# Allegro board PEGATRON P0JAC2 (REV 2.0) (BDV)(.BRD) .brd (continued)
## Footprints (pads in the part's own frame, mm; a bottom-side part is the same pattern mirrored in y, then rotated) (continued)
T_NB_HDMI_19P_16_4HL_RA_LF2
  rect 0.229x1.245 smd: 1(1.8,4.55) 3(1.4,4.55) 5(1,4.55) 7(0.6,4.55) 9(0.2,4.55) 11(-0.2,4.55) 13(-0.6,4.55) 15(-1,4.55) 17(-1.4,4.55) 19(-1.8,4.55)
  round 0.635 hole 0.381: 2(1.6,1.625) 4(1.2,3.225) 6(0.8,1.625) 8(0.4,3.225) 10(0,1.625) 12(-0.4,3.225) 14(-0.8,1.625) 16(-1.2,3.225) 18(-1.6,1.625)
  oval 0.965x2.159 hole 0.559: 20(4.2,2.425) 21(-4.2,2.425) 22(4.2,-2.425) 23(-4.2,-2.425)
TX_2R4P0402_H18
  rect 0.254x0.66 smd: 1(-0.325,-0.575) 2(-0.325,0.575) 3(0.325,-0.575) 4(0.325,0.575)
TX_BGA_6P_20_55X35
  round 0.305 smd: A1(-0.5,-0.25) A2(-0.5,0.25) B1(0,-0.25) B2(0,0.25) C1(0.5,-0.25) C2(0.5,0.25)
TX_BGA_8P_16_47X47
  round 0.229 smd: A1(-0.4,-0.4) A2(-0.4,0) A3(-0.4,0.4) B1(0,-0.4) B3(0,0.4) C1(0.4,-0.4) C2(0.4,0) C3(0.4,0.4)
TX_BGA_8P_20_75X35
  round 0.305 smd: A1(-0.75,-0.25) A2(-0.75,0.25) B1(-0.25,-0.25) B2(-0.25,0.25) C1(0.25,-0.25) C2(0.25,0.25) D1(0.75,-0.25) D2(0.75,0.25)
TX_BGA_12P_16_66X51
  round 0.229 smd: A1(-0.6,-0.4) A2(-0.6,0) A3(-0.6,0.4) B1(-0.2,-0.4) B2(-0.2,0) B3(-0.2,0.4) C1(0.2,-0.4) C2(0.2,0) C3(0.2,0.4) D1(0.6,-0.4) D2(0.6,0) D3(0.6,0.4)
TX_BGA_24P_20_118X118
  round 0.305 smd: A1(-1,-1) A2(-1,-0.5) A3(-1,0) A4(-1,0.5) A5(-1,1) B1(-0.5,-1) B3(-0.5,0) B4(-0.5,0.5) B5(-0.5,1) C1(0,-1) C2(0,-0.5) C3(0,0) C4(0,0.5) C5(0,1) D1(0.5,-1) D2(0.5,-0.5) D3(0.5,0) D4(0.5,0.5) D5(0.5,1) E1(1,-1) E2(1,-0.5) E3(1,0) E4(1,0.5) E5(1,1)
TX_BGA_169P_20_630X472_H39
  round 0.305 smd: A4(-6.75,-1.75) A6(-6.75,-0.75) A9(-6.75,0.75) A11(-6.75,1.75) AA1(3.25,-3.25) AA2(3.25,-2.75) AA3(3.25,-2.25) AA4(3.25,-1.75) AA5(3.25,-1.25) AA6(3.25,-0.75) AA7(3.25,-0.25) AA8(3.25,0.25) AA9(3.25,0.75) AA10(3.25,1.25) AA11(3.25,1.75) AA12(3.25,2.25) AA13(3.25,2.75) AA14(3.25,3.25) AE1(5.25,-3.25) AE14(5.25,3.25) AG2(6.25,-2.75) AG13(6.25,2.75) AH4(6.75,-1.75) AH6(6.75,-0.75) AH9(6.75,0.75) AH11(6.75,1.75) B2(-6.25,-2.75) B13(-6.25,2.75) D1(-5.25,-3.25) D14(-5.25,3.25) H1(-3.25,-3.25) H2(-3.25,-2.75) H3(-3.25,-2.25) H4(-3.25,-1.75) H5(-3.25,-1.25) H6(-3.25,-0.75) H7(-3.25,-0.25) H8(-3.25,0.25) H9(-3.25,0.75) H10(-3.25,1.25) H11(-3.25,1.75) H12(-3.25,2.25) H13(-3.25,2.75) H14(-3.25,3.25) J1(-2.75,-3.25) J2(-2.75,-2.75) J3(-2.75,-2.25) J4(-2.75,-1.75) J5(-2.75,-1.25) J6(-2.75,-0.75) J7(-2.75,-0.25) J8(-2.75,0.25) J9(-2.75,0.75) J10(-2.75,1.25) J11(-2.75,1.75) J12(-2.75,2.25) J13(-2.75,2.75) J14(-2.75,3.25) K1(-2.25,-3.25) K2(-2.25,-2.75) K3(-2.25,-2.25) K4(-2.25,-1.75) K5(-2.25,-1.25) K6(-2.25,-0.75) K7(-2.25,-0.25) K8(-2.25,0.25) K9(-2.25,0.75) K10(-2.25,1.25) K11(-2.25,1.75) K12(-2.25,2.25) K13(-2.25,2.75) K14(-2.25,3.25) L1(-1.75,-3.25) L2(-1.75,-2.75) L3(-1.75,-2.25) L4(-1.75,-1.75) L12(-1.75,2.25) L13(-1.75,2.75) L14(-1.75,3.25) M1(-1.25,-3.25) M2(-1.25,-2.75) M3(-1.25,-2.25) M5(-1.25,-1.25) M6(-1.25,-0.75) M7(-1.25,-0.25) M8(-1.25,0.25) M9(-1.25,0.75) M10(-1.25,1.25) M12(-1.25,2.25) M13(-1.25,2.75) M14(-1.25,3.25) N1(-0.75,-3.25) N2(-0.75,-2.75) N3(-0.75,-2.25) N5(-0.75,-1.25) N10(-0.75,1.25) N12(-0.75,2.25) N13(-0.75,2.75) N14(-0.75,3.25) P1(-0.25,-3.25) P2(-0.25,-2.75) P3(-0.25,-2.25) P5(-0.25,-1.25) P10(-0.25,1.25) P12(-0.25,2.25) P13(-0.25,2.75) P14(-0.25,3.25) R1(0.25,-3.25) R2(0.25,-2.75) R3(0.25,-2.25) R5(0.25,-1.25) R10(0.25,1.25) R12(0.25,2.25) R13(0.25,2.75) R14(0.25,3.25) T1(0.75,-3.25) T2(0.75,-2.75) T3(0.75,-2.25) T5(0.75,-1.25) T10(0.75,1.25) T12(0.75,2.25) T13(0.75,2.75) T14(0.75,3.25) U1(1.25,-3.25) U2(1.25,-2.75) U3(1.25,-2.25) U5(1.25,-1.25) U6(1.25,-0.75) U7(1.25,-0.25) U8(1.25,0.25) U9(1.25,0.75) U10(1.25,1.25) U12(1.25,2.25) U13(1.25,2.75) U14(1.25,3.25) V1(1.75,-3.25) V2(1.75,-2.75) V3(1.75,-2.25) V12(1.75,2.25) V13(1.75,2.75) V14(1.75,3.25) W1(2.25,-3.25) W2(2.25,-2.75) W3(2.25,-2.25) W4(2.25,-1.75) W5(2.25,-1.25) W6(2.25,-0.75) W7(2.25,-0.25) W8(2.25,0.25) W9(2.25,0.75) W10(2.25,1.25) W11(2.25,1.75) W12(2.25,2.25) W13(2.25,2.75) W14(2.25,3.25) Y1(2.75,-3.25) Y2(2.75,-2.75) Y3(2.75,-2.25) Y4(2.75,-1.75) Y5(2.75,-1.25) Y6(2.75,-0.75) Y7(2.75,-0.25) Y8(2.75,0.25) Y9(2.75,0.75) Y10(2.75,1.25) Y11(2.75,1.75) Y12(2.75,2.25) Y13(2.75,2.75) Y14(2.75,3.25)
TX_BGA_224P_16_244X244
  round 0.229 smd: A1(-2.8,-2.8) A2(-2.8,-2.4) A3(-2.8,-2) A4(-2.8,-1.6) A5(-2.8,-1.2) A6(-2.8,-0.8) A7(-2.8,-0.4) A8(-2.8,0) A9(-2.8,0.4) A10(-2.8,0.8) A11(-2.8,1.2) A12(-2.8,1.6) A13(-2.8,2) A14(-2.8,2.4) A15(-2.8,2.8) B1(-2.4,-2.8) B2(-2.4,-2.4) B3(-2.4,-2) B4(-2.4,-1.6) B5(-2.4,-1.2) B6(-2.4,-0.8) B7(-2.4,-0.4) B8(-2.4,0) B9(-2.4,0.4) B10(-2.4,0.8) B11(-2.4,1.2) B12(-2.4,1.6) B13(-2.4,2) B14(-2.4,2.4) B15(-2.4,2.8) C1(-2,-2.8) C2(-2,-2.4) C3(-2,-2) C4(-2,-1.6) C5(-2,-1.2) C6(-2,-0.8) C7(-2,-0.4) C8(-2,0) C9(-2,0.4) C10(-2,0.8) C11(-2,1.2) C12(-2,1.6) C13(-2,2) C14(-2,2.4) C15(-2,2.8) D1(-1.6,-2.8) D2(-1.6,-2.4) D3(-1.6,-2) D4(-1.6,-1.6) D5(-1.6,-1.2) D6(-1.6,-0.8) D7(-1.6,-0.4) D8(-1.6,0) D9(-1.6,0.4) D10(-1.6,0.8) D11(-1.6,1.2) D12(-1.6,1.6) D13(-1.6,2) D14(-1.6,2.4) D15(-1.6,2.8) E1(-1.2,-2.8) E2(-1.2,-2.4) E3(-1.2,-2) E4(-1.2,-1.6) E5(-1.2,-1.2) E6(-1.2,-0.8) E7(-1.2,-0.4) E8(-1.2,0) E9(-1.2,0.4) E10(-1.2,0.8) E11(-1.2,1.2) E12(-1.2,1.6) E13(-1.2,2) E14(-1.2,2.4) E15(-1.2,2.8) F1(-0.8,-2.8) F2(-0.8,-2.4) F3(-0.8,-2) F4(-0.8,-1.6) F5(-0.8,-1.2) F6(-0.8,-0.8) F7(-0.8,-0.4) F8(-0.8,0) F9(-0.8,0.4) F10(-0.8,0.8) F11(-0.8,1.2) F12(-0.8,1.6) F13(-0.8,2) F14(-0.8,2.4) F15(-0.8,2.8) G1(-0.4,-2.8) G2(-0.4,-2.4) G3(-0.4,-2) G4(-0.4,-1.6) G5(-0.4,-1.2) G6(-0.4,-0.8) G8(-0.4,0) G9(-0.4,0.4) G10(-0.4,0.8) G11(-0.4,1.2) G12(-0.4,1.6) G13(-0.4,2) G14(-0.4,2.4) G15(-0.4,2.8) H1(0,-2.8) H2(0,-2.4) H3(0,-2) H4(0,-1.6) H5(0,-1.2) H6(0,-0.8) H7(0,-0.4) H8(0,0) H9(0,0.4) H10(0,0.8) H11(0,1.2) H12(0,1.6) H13(0,2) H14(0,2.4) H15(0,2.8) J1(0.4,-2.8) J2(0.4,-2.4) J3(0.4,-2) J4(0.4,-1.6) J5(0.4,-1.2) J6(0.4,-0.8) J7(0.4,-0.4) J8(0.4,0) J9(0.4,0.4) J10(0.4,0.8) J11(0.4,1.2) J12(0.4,1.6) J13(0.4,2) J14(0.4,2.4) J15(0.4,2.8) K1(0.8,-2.8) K2(0.8,-2.4) K3(0.8,-2) K4(0.8,-1.6) K5(0.8,-1.2) K6(0.8,-0.8) K7(0.8,-0.4) K8(0.8,0) K9(0.8,0.4) K10(0.8,0.8) K11(0.8,1.2) K12(0.8,1.6) K13(0.8,2) K14(0.8,2.4) K15(0.8,2.8) L1(1.2,-2.8) L2(1.2,-2.4) L3(1.2,-2) L4(1.2,-1.6) L5(1.2,-1.2) L6(1.2,-0.8) L7(1.2,-0.4) L8(1.2,0) L9(1.2,0.4) L10(1.2,0.8) L11(1.2,1.2) L12(1.2,1.6) L13(1.2,2) L14(1.2,2.4) L15(1.2,2.8) M1(1.6,-2.8) M2(1.6,-2.4) M3(1.6,-2) M4(1.6,-1.6) M5(1.6,-1.2) M6(1.6,-0.8) M7(1.6,-0.4) M8(1.6,0) M9(1.6,0.4) M10(1.6,0.8) M11(1.6,1.2) M12(1.6,1.6) M13(1.6,2) M14(1.6,2.4) M15(1.6,2.8) N1(2,-2.8) N2(2,-2.4) N3(2,-2) N4(2,-1.6) N5(2,-1.2) N6(2,-0.8) N7(2,-0.4) N8(2,0) N9(2,0.4) N10(2,0.8) N11(2,1.2) N12(2,1.6) N13(2,2) N14(2,2.4) N15(2,2.8) P1(2.4,-2.8) P2(2.4,-2.4) P3(2.4,-2) P4(2.4,-1.6) P5(2.4,-1.2) P6(2.4,-0.8) P7(2.4,-0.4) P8(2.4,0) P9(2.4,0.4) P10(2.4,0.8) P11(2.4,1.2) P12(2.4,1.6) P13(2.4,2) P14(2.4,2.4) P15(2.4,2.8) R1(2.8,-2.8) R2(2.8,-2.4) R3(2.8,-2) R4(2.8,-1.6) R5(2.8,-1.2) R6(2.8,-0.8) R7(2.8,-0.4) R8(2.8,0) R9(2.8,0.4) R10(2.8,0.8) R11(2.8,1.2) R12(2.8,1.6) R13(2.8,2) R14(2.8,2.4) R15(2.8,2.8)
TX_BGA_253P_20_492X492
  round 0.305 smd: A1(-4,-4) A2(-4,-3.5) A3(-4,-3) A4(-4,-2.5) A5(-4,-2) A6(-4,-1.5) A7(-4,-1) A8(-4,-0.5) A9(-4,0) A10(-4,0.5) A11(-4,1) A12(-4,1.5) A13(-4,2) A14(-4,2.5) A15(-4,3) A16(-4,3.5) A17(-4,4) B1(-3.5,-4) B2(-3.5,-3.5) B3(-3.5,-3) B4(-3.5,-2.5) B5(-3.5,-2) B6(-3.5,-1.5) B7(-3.5,-1) B8(-3.5,-0.5) B9(-3.5,0) B10(-3.5,0.5) B11(-3.5,1) B12(-3.5,1.5) B13(-3.5,2) B14(-3.5,2.5) B15(-3.5,3) B16(-3.5,3.5) B17(-3.5,4) C1(-3,-4) C2(-3,-3.5) C3(-3,-3) C4(-3,-2.5) C5(-3,-2) C6(-3,-1.5) C7(-3,-1) C8(-3,-0.5) C9(-3,0) C10(-3,0.5) C11(-3,1) C12(-3,1.5) C13(-3,2) C14(-3,2.5) C15(-3,3) C16(-3,3.5) C17(-3,4) D1(-2.5,-4) D2(-2.5,-3.5) D3(-2.5,-3) D4(-2.5,-2.5) D5(-2.5,-2) D6(-2.5,-1.5) D7(-2.5,-1) D8(-2.5,-0.5) D9(-2.5,0) D10(-2.5,0.5) D11(-2.5,1) D12(-2.5,1.5) D13(-2.5,2) D14(-2.5,2.5) D15(-2.5,3) D16(-2.5,3.5) D17(-2.5,4) E1(-2,-4) E2(-2,-3.5) E3(-2,-3) E4(-2,-2.5) E5(-2,-2) E6(-2,-1.5) E7(-2,-1) E8(-2,-0.5) E9(-2,0) E10(-2,0.5) E11(-2,1) E12(-2,1.5) E13(-2,2) E14(-2,2.5) E15(-2,3) E16(-2,3.5) E17(-2,4) F1(-1.5,-4) F2(-1.5,-3.5) F3(-1.5,-3) F4(-1.5,-2.5) F5(-1.5,-2) F12(-1.5,1.5) F13(-1.5,2) F14(-1.5,2.5) F15(-1.5,3) F16(-1.5,3.5) F17(-1.5,4) G1(-1,-4) G2(-1,-3.5) G3(-1,-3) G4(-1,-2.5) G5(-1,-2) G12(-1,1.5) G13(-1,2) G14(-1,2.5) G15(-1,3) G16(-1,3.5) G17(-1,4) H1(-0.5,-4) H2(-0.5,-3.5) H3(-0.5,-3) H4(-0.5,-2.5) H5(-0.5,-2) H12(-0.5,1.5) H13(-0.5,2) H14(-0.5,2.5) H15(-0.5,3) H16(-0.5,3.5) H17(-0.5,4) J1(0,-4) J2(0,-3.5) J3(0,-3) J4(0,-2.5) J5(0,-2) J12(0,1.5) J13(0,2) J14(0,2.5) J15(0,3) J16(0,3.5) J17(0,4) K1(0.5,-4) K2(0.5,-3.5) K3(0.5,-3) K4(0.5,-2.5) K5(0.5,-2) K12(0.5,1.5) K13(0.5,2) K14(0.5,2.5) K15(0.5,3) K16(0.5,3.5) K17(0.5,4) L1(1,-4) L2(1,-3.5) L3(1,-3) L4(1,-2.5) L5(1,-2) L12(1,1.5) L13(1,2) L14(1,2.5) L15(1,3) L16(1,3.5) L17(1,4) M1(1.5,-4) M2(1.5,-3.5) M3(1.5,-3) M4(1.5,-2.5) M5(1.5,-2) M6(1.5,-1.5) M7(1.5,-1) M8(1.5,-0.5) M9(1.5,0) M10(1.5,0.5) M11(1.5,1) M12(1.5,1.5) M13(1.5,2) M14(1.5,2.5) M15(1.5,3) M16(1.5,3.5) M17(1.5,4) N1(2,-4) N2(2,-3.5) N3(2,-3) N4(2,-2.5) N5(2,-2) N6(2,-1.5) N7(2,-1) N8(2,-0.5) N9(2,0) N10(2,0.5) N11(2,1) N12(2,1.5) N13(2,2) N14(2,2.5) N15(2,3) N16(2,3.5) N17(2,4) P1(2.5,-4) P2(2.5,-3.5) P3(2.5,-3) P4(2.5,-2.5) P5(2.5,-2) P6(2.5,-1.5) P7(2.5,-1) P8(2.5,-0.5) P9(2.5,0) P10(2.5,0.5) P11(2.5,1) P12(2.5,1.5) P13(2.5,2) P14(2.5,2.5) P15(2.5,3) P16(2.5,3.5) P17(2.5,4) R1(3,-4) R2(3,-3.5) R3(3,-3) R4(3,-2.5) R5(3,-2) R6(3,-1.5) R7(3,-1) R8(3,-0.5) R9(3,0) R10(3,0.5) R11(3,1) R12(3,1.5) R13(3,2) R14(3,2.5) R15(3,3) R16(3,3.5) R17(3,4) T1(3.5,-4) T2(3.5,-3.5) T3(3.5,-3) T4(3.5,-2.5) T5(3.5,-2) T6(3.5,-1.5) T7(3.5,-1) T8(3.5,-0.5) T9(3.5,0) T10(3.5,0.5) T11(3.5,1) T12(3.5,1.5) T13(3.5,2) T14(3.5,2.5) T15(3.5,3) T16(3.5,3.5) T17(3.5,4) U1(4,-4) U2(4,-3.5) U3(4,-3) U4(4,-2.5) U5(4,-2) U6(4,-1.5) U7(4,-1) U8(4,-0.5) U9(4,0) U10(4,0.5) U11(4,1) U12(4,1.5) U13(4,2) U14(4,2.5) U15(4,3) U16(4,3.5) U17(4,4)
TX_BTOB_60P_16_4H_F_PANA
  rect 0.229x0.508 smd: 1(-5.8,-1.05) 2(-5.8,1.05) 3(-5.4,-1.05) 4(-5.4,1.05) 5(-5,-1.05) 6(-5,1.05) 7(-4.6,-1.05) 8(-4.6,1.05) 9(-4.2,-1.05) 10(-4.2,1.05) 11(-3.8,-1.05) 12(-3.8,1.05) 13(-3.4,-1.05) 14(-3.4,1.05) 15(-3,-1.05) 16(-3,1.05) 17(-2.6,-1.05) 18(-2.6,1.05) 19(-2.2,-1.05) 20(-2.2,1.05) 21(-1.8,-1.05) 22(-1.8,1.05) 23(-1.4,-1.05) 24(-1.4,1.05) 25(-1,-1.05) 26(-1,1.05) 27(-0.6,-1.05) 28(-0.6,1.05) 29(-0.2,-1.05) 30(-0.2,1.05) 31(0.2,-1.05) 32(0.2,1.05) 33(0.6,-1.05) 34(0.6,1.05) 35(1,-1.05) 36(1,1.05) 37(1.4,-1.05) 38(1.4,1.05) 39(1.8,-1.05) 40(1.8,1.05) 41(2.2,-1.05) 42(2.2,1.05) 43(2.6,-1.05) 44(2.6,1.05) 45(3,-1.05) 46(3,1.05) 47(3.4,-1.05) 48(3.4,1.05) 49(3.8,-1.05) 50(3.8,1.05) 51(4.2,-1.05) 52(4.2,1.05) 53(4.6,-1.05) 54(4.6,1.05) 55(5,-1.05) 56(5,1.05) 57(5.4,-1.05) 58(5.4,1.05) 59(5.8,-1.05) 60(5.8,1.05)
  rect 0.787x0.787 smd: 61(6.85,-0.91) 62(-6.85,-0.91) 63(6.85,0.91) 64(-6.85,0.91)
TX_C0201
  rect 0.305x0.305 smd: 1(-0.254,0) 2(0.254,0)
TX_C0201_H14
  rect 0.305x0.305 smd: 1(-0.254,0) 2(0.254,0)
TX_C0402
  rect 0.432x0.508 smd: 1(-0.432,0) 2(0.432,0)
TX_C0402_H24
  rect 0.432x0.508 smd: 1(-0.432,0) 2(0.432,0)
TX_C0402_H26
  rect 0.432x0.508 smd: 1(-0.432,0) 2(0.432,0)
TX_C0402_H28
  rect 0.432x0.508 smd: 1(-0.432,0) 2(0.432,0)
TX_C0603
  rect 0.559x0.889 smd: 1(-0.67,0) 2(0.67,0)
TX_C0603_H37
  rect 0.559x0.889 smd: 1(-0.67,0) 2(0.67,0)
TX_C0603_H39
  rect 0.559x0.889 smd: 1(-0.67,0) 2(0.67,0)
TX_C0805
  rect 0.813x1.397 smd: 1(0.9,0) 2(-0.9,0)
TX_C0805_H49
  rect 0.813x1.397 smd: 1(0.9,0) 2(-0.9,0)
TX_C3216_H47
  rect 1.803x1.194 smd: 1(1.613,0) 2(-1.613,0)
TX_C3528_SANYO_H47
  rect 1.422x2.21 smd: 1(1.567,0) 2(-1.567,0)
TX_CHOKE_4P_49X39
  rect 0.711x0.305 smd: 1(-0.625,0.275) 2(0.625,0.275) 3(0.625,-0.275) 4(-0.625,-0.275)
TX_DFN1006_2
  rect 0.406x0.711 smd: 1(-0.35,0) 2(0.35,0)
TX_DFN_6P_26_79X79_2PAD_IR
  rect 0.381x0.457 smd: 1(-0.65,-0.925) 2(0,-0.925) 3(0.65,-0.925) 4(0.65,0.925) 5(0,0.925) 6(-0.65,0.925)
  rect 1.041x0.965 smd: 7(-0.28,0.002)
  rect 0.229x0.787 smd: 8(0.735,0.002)
TX_DFN_6P_26_S79_2PAD_H31
  rect 0.381x0.457 smd: 1(-0.65,-0.922) 2(0,-0.922) 3(0.65,-0.922) 4(0.65,0.922) 5(0,0.922) 6(-0.65,0.922)
  rect 1.092x0.965 smd: 7(-0.23,0)
  rect 0.203x0.838 smd: 8(0.716,-0.005)
TX_DFN_8P_18_79X79
  rect 0.279x0.711 smd: 1(-0.675,-0.799)
  rect 0.279x0.61 smd: 2(-0.225,-0.85) 3(0.225,-0.85) 4(0.675,-0.85) 5(0.675,0.85) 6(0.225,0.85) 7(-0.225,0.85) 8(-0.675,0.85)
TX_DFN_8P_50_197X236_PAD_WI
  rect 0.406x1.067 smd: 1(-1.905,-2.833) 2(-0.635,-2.833) 3(0.635,-2.833) 4(1.905,-2.833) 5(1.905,2.833) 6(0.635,2.833) 7(-0.635,2.833) 8(-1.905,2.833)
  rect 4.343x3.454 smd: 9(0,0)
TX_DIODE_2P_39X24_INFINEON
  rect 0.356x0.61 smd: 1(-0.325,0) 2(0.325,0)
TX_ESD_2P_33_39X24_H20
  rect 0.559x0.61 smd: 1(-0.425,0) 2(0.425,0)
TX_FPC_6P_20_2HOLD_ACES
  rect 0.305x0.787 smd: 1(-1.25,2.5) 2(-0.75,2.5) 3(-0.25,2.5) 4(0.25,2.5) 5(0.75,2.5) 6(1.25,2.5)
  rect 0.406x0.787 smd: 7(-2.25,0) 8(2.25,0)
TX_FPC_12P_20_2HOLD_RA_PTWO
  rect 0.305x0.711 smd: 1(-2.75,2.745) 2(-2.25,2.745) 3(-1.75,2.745) 4(-1.25,2.745) 5(-0.75,2.745) 6(-0.25,2.745) 7(0.25,2.745) 8(0.75,2.745) 9(1.25,2.745) 10(1.75,2.745) 11(2.25,2.745) 12(2.75,2.745)
  rect 0.406x0.889 smd: 13(-3.62,0) 14(3.62,0)
TX_FPC_18P_20_2H_RA_B
  rect 0.305x0.787 smd: 1(-4.25,2.5) 2(-3.75,2.5) 3(-3.25,2.5) 4(-2.75,2.5) 5(-2.25,2.5) 6(-1.75,2.5) 7(-1.25,2.5) 8(-0.75,2.5) 9(-0.25,2.5) 10(0.25,2.5) 11(0.75,2.5) 12(1.25,2.5) 13(1.75,2.5) 14(2.25,2.5) 15(2.75,2.5) 16(3.25,2.5) 17(3.75,2.5) 18(4.25,2.5)
  rect 0.406x0.787 smd: 19(-5.25,0) 20(5.25,0)
TX_FPC_21P_24_2H_RA_SUNG
  rect 0.305x0.787 smd: 1(-3,-0.375) 3(-2.4,-0.375) 5(-1.8,-0.375) 7(-1.2,-0.375) 9(-0.6,-0.375) 11(0,-0.375) 13(0.6,-0.375) 15(1.2,-0.375) 17(1.8,-0.375) 19(2.4,-0.375) 21(3,-0.375)
  rect 0.305x0.66 smd: 2(-2.7,2.5) 4(-2.1,2.5) 6(-1.5,2.5) 8(-0.9,2.5) 10(-0.3,2.5) 12(0.3,2.5) 14(0.9,2.5) 16(1.5,2.5) 18(2.1,2.5) 20(2.7,2.5)
  rect 0.305x1.143 smd: 22(-3.65,0) 23(3.65,0)
TX_FPC_39P_24_2HOLD_RA_HSR
  rect 0.305x0.787 smd: 1(-5.7,-0.275) 3(-5.1,-0.275) 5(-4.5,-0.275) 7(-3.9,-0.275) 9(-3.3,-0.275) 11(-2.7,-0.275) 13(-2.1,-0.275) 15(-1.5,-0.275) 17(-0.9,-0.275) 19(-0.3,-0.275) 21(0.3,-0.275) 23(0.9,-0.275) 25(1.5,-0.275) 27(2.1,-0.275) 29(2.7,-0.275) 31(3.3,-0.275) 33(3.9,-0.275) 35(4.5,-0.275) 37(5.1,-0.275) 39(5.7,-0.275)
  rect 0.305x0.66 smd: 2(-5.4,2.6) 4(-4.8,2.6) 6(-4.2,2.6) 8(-3.6,2.6) 10(-3,2.6) 12(-2.4,2.6) 14(-1.8,2.6) 16(-1.2,2.6) 18(-0.6,2.6) 20(0,2.6) 22(0.6,2.6) 24(1.2,2.6) 26(1.8,2.6) 28(2.4,2.6) 30(3,2.6) 32(3.6,2.6) 34(4.2,2.6) 36(4.8,2.6) 38(5.4,2.6)
  rect 0.406x0.94 smd: 40(-6.4,0) 41(6.4,0)
TX_FPC_CON_34P_31_2HD_T
  rect 0.508x1.092 smd: 1(-13.2,1.65) 2(-12.4,1.65) 3(-11.6,1.65) 4(-10.8,1.65) 5(-10,1.65) 6(-9.2,1.65) 7(-8.4,1.65) 8(-7.6,1.65) 9(-6.8,1.65) 10(-6,1.65) 11(-5.2,1.65) 12(-4.4,1.65) 13(-3.6,1.65) 14(-2.8,1.65) 15(-2,1.65) 16(-1.2,1.65) 17(-0.4,1.65) 18(0.4,1.65) 19(1.2,1.65) 20(2,1.65) 21(2.8,1.65) 22(3.6,1.65) 23(4.4,1.65) 24(5.2,1.65) 25(6,1.65) 26(6.8,1.65) 27(7.6,1.65) 28(8.4,1.65) 29(9.2,1.65) 30(10,1.65) 31(10.8,1.65) 32(11.6,1.65) 33(12.4,1.65) 34(13.2,1.65)
  rect 2.388x2.21 smd: 35(15.6,0) 36(-15.6,0)
TX_FUSE_2P_39X20_H14
  rect 0.584x0.559 smd: 1(-0.483,0) 2(0.483,0)
TX_INDUCTOR_2P_98X79_TAIYO
  rect 0.787x2.007 smd: 1(-1,0) 2(1,0)
TX_INDUCTOR_2P_213X205_H59
  rect 1.905x2.489 smd: 1(-2.047,0) 2(2.047,0)
TX_L0402_H24
  rect 0.432x0.508 smd: 1(-0.432,0) 2(0.432,0)
TX_L0603_H26
  rect 0.559x0.889 smd: 1(-0.775,0) 2(0.775,0)
TX_L0805_H43
  rect 0.813x1.397 smd: 1(-0.9,0) 2(0.9,0)
TX_L1008_MURA
  rect 1.321x2.007 smd: 1(-1.217,0) 2(1.217,0)
TX_L1008_TAIYO_H47
  rect 1.245x2.007 smd: 1(-1.267,0) 2(1.267,0)
TX_LGA_96P_20_12PAD_FOXCO
  rect 0.305x0.508 smd: 1(-6.75,-5.6) 2(-6.25,-5.6) 3(-5.75,-5.6) 4(-5.25,-5.6) 5(-4.75,-5.6) 6(-4.25,-5.6) 7(-3.75,-5.6) 8(-3.25,-5.6) 9(-2.75,-5.6) 10(-2.25,-5.6) 11(-1.75,-5.6) 12(-1.25,-5.6) 13(-0.75,-5.6) 14(-0.25,-5.6) 15(0.25,-5.6) 16(0.75,-5.6) 17(1.25,-5.6) 18(1.75,-5.6) 19(2.25,-5.6) 20(2.75,-5.6) 21(3.25,-5.6) 22(3.75,-5.6) 23(4.25,-5.6) 24(4.75,-5.6) 25(5.25,-5.6) 26(5.75,-5.6) 27(6.25,-5.6) 28(6.75,-5.6) 49(6.75,5.6) 50(6.25,5.6) 51(5.75,5.6) 52(5.25,5.6) 53(4.75,5.6) 54(4.25,5.6) 55(3.75,5.6) 56(3.25,5.6) 57(2.75,5.6) 58(2.25,5.6) 59(1.75,5.6) 60(1.25,5.6) 61(0.75,5.6) 62(0.25,5.6) 63(-0.25,5.6) 64(-0.75,5.6) 65(-1.25,5.6) 66(-1.75,5.6) 67(-2.25,5.6) 68(-2.75,5.6) 69(-3.25,5.6) 70(-3.75,5.6) 71(-4.25,5.6) 72(-4.75,5.6) 73(-5.25,5.6) 74(-5.75,5.6) 75(-6.25,5.6) 76(-6.75,5.6)
  rect 0.508x0.305 smd: 29(7.6,-4.75) 30(7.6,-4.25) 31(7.6,-3.75) 32(7.6,-3.25) 33(7.6,-2.75) 34(7.6,-2.25) 35(7.6,-1.75) 36(7.6,-1.25) 37(7.6,-0.75) 38(7.6,-0.25) 39(7.6,0.25) 40(7.6,0.75) 41(7.6,1.25) 42(7.6,1.75) 43(7.6,2.25) 44(7.6,2.75) 45(7.6,3.25) 46(7.6,3.75) 47(7.6,4.25) 48(7.6,4.75) 77(-7.6,4.75) 78(-7.6,4.25) 79(-7.6,3.75) 80(-7.6,3.25) 81(-7.6,2.75) 82(-7.6,2.25) 83(-7.6,1.75) 84(-7.6,1.25) 85(-7.6,0.75) 86(-7.6,0.25) 87(-7.6,-0.25) 88(-7.6,-0.75) 89(-7.6,-1.25) 90(-7.6,-1.75) 91(-7.6,-2.25) 92(-7.6,-2.75) 93(-7.6,-3.25) 94(-7.6,-3.75) 95(-7.6,-4.25) 96(-7.6,-4.75)
  rect 0.711x0.711 smd: G1(-7.5,-5.5) G2(7.5,-5.5) G3(7.5,5.5) G4(-7.5,5.5)
  rect 2.997x2.997 smd: G5(-4.95,-1.65) G6(-1.65,-1.65) G7(1.65,-1.65) G8(4.95,-1.65) G9(-4.95,1.65) G10(-1.65,1.65) G11(1.65,1.65) G12(4.95,1.65)
TX_MICRO_SD_8P_11HOLD
  rect 0.66x0.991 smd: 1(2.3,7.425) 2(1.4,7.425) 3(0.5,7.425) 4(-0.4,7.425) 5(-1.3,7.425) 6(-2.2,7.425) 7(-3.1,7.425) 8(-4,7.425)
  rect 0.991x0.838 smd: 9(6.975,-4.4) 10(-6.975,-4.4) 13(-6.975,-2.475)
  rect 0.889x1.702 smd: 11(-7.15,7.075) 14(-7.15,-6.625) 15(7.15,7.075) 18(7.15,-6.625)
  rect 0.94x1.397 smd: 12(-7,0.475)
  rect 1.118x1.397 smd: 16(6.735,3.175)
  rect 0.813x1.397 smd: 17(6.887,-2.275)
  rect 0.889x0.991 smd: 19(-5.575,7.425)
TX_MICROPHONE_6P_148X186_KN
  round 0.914 smd: 1(-1.17,1.65) 2(-1.17,0) 3(-1.17,-1.65) 4(1.17,-1.65) 5(1.17,0)
  custom 0.28x0.28 smd: 6(1.17,1.65)
TX_OPLGA_6P_24_71X93_CAPELL
  rect 0.406x0.991 smd: 1(-0.6,-1.125) 2(0,-1.125) 3(0.6,-1.125) 4(0.6,1.125) 5(0,1.125) 6(-0.6,1.125)
TX_POWERDI123
  rect 0.889x1.397 smd: 1(-1.605,0)
  rect 2.21x1.397 smd: 2(0.945,0)
TX_QFN_10P_20_79X61
  rect 0.33x0.508 smd: 1(-0.775,-0.595)
  rect 0.279x0.508 smd: 2(-0.25,-0.595) 3(0.25,-0.595) 4(0.75,-0.595) 6(0.75,0.595) 7(0.25,0.595) 8(-0.25,0.595) 9(-0.75,0.595)
  rect 0.508x0.279 smd: 5(0.82,0) 10(-0.82,0)
TX_QFN_16P_20_S118_P_KT_5V
  rect 0.279x0.61 smd: 1(-0.75,-1.35) 2(-0.25,-1.35) 3(0.25,-1.35) 4(0.75,-1.35) 9(0.75,1.35) 10(0.25,1.35) 11(-0.25,1.35) 12(-0.75,1.35)
  rect 0.61x0.279 smd: 5(1.35,-0.75) 6(1.35,-0.25) 7(1.35,0.25) 8(1.35,0.75) 13(-1.35,0.75) 14(-1.35,0.25) 15(-1.35,-0.25) 16(-1.35,-0.75)
  rect 1.727x1.727 smd: 17(0,0)
  round 0.61 hole 0.305: 18(-0.5,0.5) 19(0.5,0.5) 20(0,0) 21(-0.5,-0.5) 22(0.5,-0.5)
TX_QFN_16P_26_S157_PD_TI_4V
  rect 0.381x0.61 smd: 1(-0.975,-1.85) 2(-0.325,-1.85) 3(0.325,-1.85) 4(0.975,-1.85) 9(0.975,1.85) 10(0.325,1.85) 11(-0.325,1.85) 12(-0.975,1.85)
  rect 0.61x0.381 smd: 5(1.85,-0.975) 6(1.85,-0.325) 7(1.85,0.325) 8(1.85,0.975) 13(-1.85,0.975) 14(-1.85,0.325) 15(-1.85,-0.325) 16(-1.85,-0.975)
  rect 2.642x2.642 smd: 17(0,0)
  round 0.61 hole 0.305: 18(-1.016,1.016) 19(1.016,1.016) 20(-1.016,-1.016) 21(1.016,-1.016)
TX_QFN_24P_16_S118_P_INVH37
  rect 0.229x0.406 smd: 1(-1,-1.447) 6(1,-1.447) 13(1,1.447) 18(-1,1.447)
  rect 0.229x0.508 smd: 2(-0.6,-1.396) 3(-0.2,-1.396) 4(0.2,-1.396) 5(0.6,-1.396) 14(0.6,1.396) 15(0.2,1.396) 16(-0.2,1.396) 17(-0.6,1.396)
  rect 0.406x0.229 smd: 7(1.447,-1) 12(1.447,1) 19(-1.447,1) 24(-1.447,-1)
  rect 0.508x0.229 smd: 8(1.396,-0.6) 9(1.396,-0.2) 10(1.396,0.2) 11(1.396,0.6) 20(-1.396,0.6) 21(-1.396,0.2) 22(-1.396,-0.2) 23(-1.396,-0.6)
TX_QFN_24P_20_S157_P_QU_4V
  rect 0.279x0.61 smd: 1(-1.25,-1.85) 2(-0.75,-1.85) 3(-0.25,-1.85) 4(0.25,-1.85) 5(0.75,-1.85) 6(1.25,-1.85) 13(1.25,1.85) 14(0.75,1.85) 15(0.25,1.85) 16(-0.25,1.85) 17(-0.75,1.85) 18(-1.25,1.85)
  rect 0.61x0.279 smd: 7(1.85,-1.25) 8(1.85,-0.75) 9(1.85,-0.25) 10(1.85,0.25) 11(1.85,0.75) 12(1.85,1.25) 19(-1.85,1.25) 20(-1.85,0.75) 21(-1.85,0.25) 22(-1.85,-0.25) 23(-1.85,-0.75) 24(-1.85,-1.25)
  rect 2.743x2.743 smd: 25(0,0)
  round 0.61 hole 0.305: 26(-1.067,1.067) 27(1.067,1.067) 28(-1.067,-1.067) 29(1.067,-1.067)
TX_QFN_48P_16_S236_P_RE_10V
  rect 0.229x0.61 smd: 1(-2.2,-2.85) 2(-1.8,-2.85) 3(-1.4,-2.85) 4(-1,-2.85) 5(-0.6,-2.85) 6(-0.2,-2.85) 7(0.2,-2.85) 8(0.6,-2.85) 9(1,-2.85) 10(1.4,-2.85) 11(1.8,-2.85) 12(2.2,-2.85) 25(2.2,2.85) 26(1.8,2.85) 27(1.4,2.85) 28(1,2.85) 29(0.6,2.85) 30(0.2,2.85) 31(-0.2,2.85) 32(-0.6,2.85) 33(-1,2.85) 34(-1.4,2.85) 35(-1.8,2.85) 36(-2.2,2.85)
  rect 0.61x0.229 smd: 13(2.85,-2.2) 14(2.85,-1.8) 15(2.85,-1.4) 16(2.85,-1) 17(2.85,-0.6) 18(2.85,-0.2) 19(2.85,0.2) 20(2.85,0.6) 21(2.85,1) 22(2.85,1.4) 23(2.85,1.8) 24(2.85,2.2) 37(-2.85,2.2) 38(-2.85,1.8) 39(-2.85,1.4) 40(-2.85,1) 41(-2.85,0.6) 42(-2.85,0.2) 43(-2.85,-0.2) 44(-2.85,-0.6) 45(-2.85,-1) 46(-2.85,-1.4) 47(-2.85,-1.8) 48(-2.85,-2.2)
  rect 4.648x4.648 smd: 49(0,0)
  round 0.61 hole 0.305: 50(-2.019,2.019) 51(0,2.019) 52(2.019,2.019) 53(-2.019,0) 54(-0.673,0) 55(0.673,0) 56(2.019,0) 57(-2.019,-2.019) 58(0,-2.019) 59(2.019,-2.019)
TX_QFN_48P_20_S276_P_QL_16V
  rect 0.279x0.61 smd: 1(-2.75,-3.35) 2(-2.25,-3.35) 3(-1.75,-3.35) 4(-1.25,-3.35) 5(-0.75,-3.35) 6(-0.25,-3.35) 7(0.25,-3.35) 8(0.75,-3.35) 9(1.25,-3.35) 10(1.75,-3.35) 11(2.25,-3.35) 12(2.75,-3.35) 25(2.75,3.35) 26(2.25,3.35) 27(1.75,3.35) 28(1.25,3.35) 29(0.75,3.35) 30(0.25,3.35) 31(-0.25,3.35) 32(-0.75,3.35) 33(-1.25,3.35) 34(-1.75,3.35) 35(-2.25,3.35) 36(-2.75,3.35)
  rect 0.61x0.279 smd: 13(3.35,-2.75) 14(3.35,-2.25) 15(3.35,-1.75) 16(3.35,-1.25) 17(3.35,-0.75) 18(3.35,-0.25) 19(3.35,0.25) 20(3.35,0.75) 21(3.35,1.25) 22(3.35,1.75) 23(3.35,2.25) 24(3.35,2.75) 37(-3.35,2.75) 38(-3.35,2.25) 39(-3.35,1.75) 40(-3.35,1.25) 41(-3.35,0.75) 42(-3.35,0.25) 43(-3.35,-0.25) 44(-3.35,-0.75) 45(-3.35,-1.25) 46(-3.35,-1.75) 47(-3.35,-2.25) 48(-3.35,-2.75)
  rect 5.309x5.309 smd: 49(0,0)
  round 0.61 hole 0.305: 50(-1.5,1.5) 51(-0.5,1.5) 52(0.5,1.5) 53(1.5,1.5) 54(1.5,0.5) 55(0.5,0.5) 56(-0.5,0.5) 57(-1.5,0.5) 58(-1.5,-0.5) 59(-0.5,-0.5) 60(0.5,-0.5) 61(1.5,-0.5) 62(1.5,-1.5) 63(0.5,-1.5) 64(-0.5,-1.5) 65(-1.5,-1.5)
TX_QFP_64P_16_354X354_H63
  rect 0.229x1.499 smd: 1(-3,-4.36) 2(-2.6,-4.36) 3(-2.2,-4.36) 4(-1.8,-4.36) 5(-1.4,-4.36) 6(-1,-4.36) 7(-0.6,-4.36) 8(-0.2,-4.36) 9(0.2,-4.36) 10(0.6,-4.36) 11(1,-4.36) 12(1.4,-4.36) 13(1.8,-4.36) 14(2.2,-4.36) 15(2.6,-4.36) 16(3,-4.36) 33(3,4.36) 34(2.6,4.36) 35(2.2,4.36) 36(1.8,4.36) 37(1.4,4.36) 38(1,4.36) 39(0.6,4.36) 40(0.2,4.36) 41(-0.2,4.36) 42(-0.6,4.36) 43(-1,4.36) 44(-1.4,4.36) 45(-1.8,4.36) 46(-2.2,4.36) 47(-2.6,4.36) 48(-3,4.36)
  rect 1.499x0.229 smd: 17(4.36,-3) 18(4.36,-2.6) 19(4.36,-2.2) 20(4.36,-1.8) 21(4.36,-1.4) 22(4.36,-1) 23(4.36,-0.6) 24(4.36,-0.2) 25(4.36,0.2) 26(4.36,0.6) 27(4.36,1) 28(4.36,1.4) 29(4.36,1.8) 30(4.36,2.2) 31(4.36,2.6) 32(4.36,3) 49(-4.36,3) 50(-4.36,2.6) 51(-4.36,2.2) 52(-4.36,1.8) 53(-4.36,1.4) 54(-4.36,1) 55(-4.36,0.6) 56(-4.36,0.2) 57(-4.36,-0.2) 58(-4.36,-0.6) 59(-4.36,-1) 60(-4.36,-1.4) 61(-4.36,-1.8) 62(-4.36,-2.2) 63(-4.36,-2.6) 64(-4.36,-3)
TX_R0201_0OHM_H10
  rect 0.305x0.305 smd: 1(-0.254,0) 2(0.254,0)
TX_R0201_H10
  rect 0.305x0.305 smd: 1(-0.254,0) 2(0.254,0)
TX_R0402
  rect 0.432x0.508 smd: 1(-0.432,0) 2(0.432,0)
TX_R0402_0OHM
  rect 0.432x0.508 smd: 1(-0.432,0) 2(0.432,0)
TX_R0402_H22
  rect 0.432x0.508 smd: 1(-0.432,0) 2(0.432,0)
TX_R0402_SHORT_12MIL
  rect 0.457x0.508 smd: 1(-0.419,0) 2(0.419,0)
TX_R0603_0OHM_H24
  rect 0.559x0.889 smd: 1(-0.67,0) 2(0.67,0)
TX_R0603_H24
  rect 0.559x0.889 smd: 1(-0.67,0) 2(0.67,0)
TX_R0805_H24
  rect 0.813x1.397 smd: 1(-0.9,0) 2(0.9,0)
TX_R0805_H26
  rect 0.813x1.397 smd: 1(-0.9,0) 2(0.9,0)
TX_R1206_H30
  rect 0.864x1.803 smd: 1(-1.325,0) 2(1.325,0)
TX_SC70_S6_H47
  rect 0.356x0.94 smd: 1(-0.65,-1.19) 2(0,-1.19) 3(0.65,-1.19) 4(0.65,1.19) 5(0,1.19) 6(-0.65,1.19)
TX_SO8_H69
  rect 0.635x1.549 smd: 1(-1.91,-2.83) 2(-0.64,-2.83) 3(0.63,-2.83) 4(1.9,-2.83) 5(1.91,2.83) 6(0.64,2.83) 7(-0.63,2.83) 8(-1.9,2.83)
TX_SOIC_8P_26_122X193
  rect 0.356x1.448 smd: 1(-0.975,-2.335) 2(-0.325,-2.335) 3(0.325,-2.335) 4(0.975,-2.335) 5(0.975,2.335) 6(0.325,2.335) 7(-0.325,2.335) 8(-0.975,2.335)
TX_SOT23_2D4_H44
  rect 0.711x1.016 smd: 1(-0.95,-1.301) 2(0.95,-1.301) 3(0,1.301)
TX_SOT23_2D4_H57
  rect 0.711x1.016 smd: 1(-0.95,-1.301) 2(0.95,-1.301) 3(0,1.301)
TX_SOT23_S5_H57
  rect 1.118x0.61 smd: 1(1.45,-0.95) 2(1.45,0) 3(1.45,0.95) 4(-1.45,0.95) 5(-1.45,-0.95)
TX_SOT323
  rect 0.914x0.813 smd: 1(0.97,-0.65) 2(0.97,0.65) 3(-0.97,0)
TX_SW_3P_45_2HOLD
  rect 0.787x1.245 smd: 1(-1.15,1.815) 2(0,1.815) 3(1.15,1.815)
  oval 0.711x1.143 hole 0.406: 4(-2.7,0) 5(2.7,0)
TX_USB_5P_4HOLD_RA_ACON
  rect 0.457x1.092 smd: 1(-1.3,2.52) 2(-0.65,2.52) 3(0,2.52) 4(0.65,2.52) 5(1.3,2.52)
  oval 0.965x2.057 hole 0.559: 6(-4.95,2) 7(4.95,2)
  oval 0.965x2.362 hole 0.559: 8(-4.95,-2) 9(4.95,-2)
TX_VMT3_3P_ROHM
  rect 0.229x0.787 smd: 1(-0.4,-0.547) 2(0.4,-0.547)
  rect 0.33x0.787 smd: 3(0,0.547)
TX_WTOB_4P_31_2H_ENT
  rect 0.508x0.991 smd: 1(1.2,1.95) 2(0.4,1.95) 3(-0.4,1.95) 4(-1.2,1.95)
  rect 1.194x1.702 smd: 5(-2.5,0) 6(2.5,0)
TX_WTOB_4P_49_2HOLD_RA_H88
  rect 0.787x2.007 smd: 1(1.875,4.05) 2(0.625,4.05) 3(-0.625,4.05) 4(-1.875,4.05)
  rect 2.007x2.489 smd: 5(-4.075,0) 6(4.075,0)
TX_WTOB_6P_79_2HOLD_ACE
  rect 0.559x1.295 smd: 1(5,5.025) 2(3,5.025) 3(1,5.025) 4(-1,5.025) 5(-3,5.025) 6(-5,5.025)
  rect 1.295x2.057 smd: 7(8.1,0) 8(-8.1,0)
TX_WTOB_9P_79_2HOLD_ACE
  rect 0.559x1.295 smd: 1(8,5.025) 2(6,5.025) 3(4,5.025) 4(2,5.025) 5(0,5.025) 6(-2,5.025) 7(-4,5.025) 8(-6,5.025) 9(-8,5.025)
  rect 1.295x2.057 smd: 10(-11.1,0) 11(11.1,0)
TX_XTAL_2P_126X59
  rect 0.991x1.803 smd: 1(-1.25,0) 2(1.25,0)
TX_XTAL_4P_126X98_EPSON
  rect 1.397x1.143 smd: 1(-1.1,-0.8) 2(1.1,-0.8) 3(1.1,0.8) 4(-1.1,0.8)
unnamed
  round 0.991 hole 0.991 unplated: (0,0)
unnamed#3
  round 1.016 smd: 1(0,0)

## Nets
3VO: C8111.1 C8112.1 C8113.1 R8120.2 R8122.1 SR8100.1 T8103.1 U8101.D1
3VO_EN: Q8101.3 R8121.2 R8129.2 U8101.A3
3VO_FB: SR8100.2 U8101.D2
3VO_LX1: L8101.1 U8101.A1
3VO_LX2: L8101.2 U8101.C1
3VO_PWRGD: R8120.1 T8102.1 U8101.C3
3VO_SS: C8110.1 U8101.D3
3VO_VIN: C8109.1 C8114.1 CE8102.1 R8116.2 R8121.1 T8101.1 U8101.A2
5V_EN: Q8100.3 R8114.2 U8100.11
5V_FB: C8100.2 R8100.1 R8103.2 U8100.14
5V_USB_PAD: C5216.1 C5217.1 CE5201.1 CE5202.1 CON5201.1 L5202.2
+5VO: C8102.1 C8105.1 C8107.1 C8108.1 CE8100.1 CE8101.1 JP8100.1 JP8102.1 U8100.1 U8100.15 U8100.16
+V1P0A: C2759.1 C2760.1 C2761.1 C8301.1 C8332.1 C8333.1 Q8301.1 Q8301.2 Q8301.5 Q8301.6 Q8301.7 Q8302.1 Q8302.2 Q8302.5 Q8302.6 Q8302.7 R8208.1 T8202.1 U2400.P15 U2400.P17 U2400.P19 U2400.T18 U2400.W1 U8201.C11
+V1P0A_FB: JP8201.2 U8201.M10
+V1P0A_LX: L8211.2 U8201.P12 U8201.R12
+V1P0A_PMIC: C8230.1 C8231.1 C8232.1 C8233.1 JP8201.1 L8211.1 R8208.2
+V1P0S: C2752.1 C2753.1 C2754.1 C2776.1 C2777.1 JP8306.1 R2508.1 R2710.1 R2715.1 R8313.2 R8501.1 R8505.1 R8506.1 R8526.1 R8527.1 R8530.1 U2400.AA1 U2400.AN1 U2400.AP2 U2400.BF32 U2400.M14 U2400.M36 U2400.N1 U2400.P2
+V1P0S_EN: Q8301.3 R8314.1 U8201.M11
+V1P0S_LC_GPIO_SI0: R2710.2 R2714.1 U2400.BD14
+V1P0S_PCIE_SATA: R2715.2 R2716.1 U2400.BB2 U2400.BB15 U2400.BC1 U2400.BF2 U2400.BG1
+V1P0S_PMIC: C8331.1 JP8303.1 Q8301.4 Q8301.8 R8313.1
+V1P0S_SENSE: JP8303.2 U8201.L12
+V1P0SX: C2717.1 C2718.1 C2727.1 C2728.1 C2729.1 C2730.1 C2774.1 JP8307.1 R8316.2 U2400.A9 U2400.A13 U2400.AT19 U2400.AT21 U2400.AU14 U2400.AV2 U2400.AW1 U2400.AW15 U2400.B10 U2400.B14 U2400.BV26 U2400.BW27
+V1P0SX_EN: Q8302.3 R8315.1 U8201.N11
+V1P0SX_PMIC: C8334.1 JP8304.1 Q8302.4 Q8302.8 R8316.1
+V1P0SX_S: C2766.1 C2767.1 C2768.1 C2771.1 C2772.1 C2773.1 JP8306.2 JP8307.2 U2400.A41 U2400.A43 U2400.AC43 U2400.AH44 U2400.AW44 U2400.B40 U2400.BV40 U2400.BW41 U2400.BW43
+V1P0SX_SENSE: JP8304.2 U8201.K12
+V1P2A: C2723.1 R8305.2 T8306.1 U2400.R1
+V1P2A_PMIC: C8313.1 R8305.1 U8201.C7
+V1P2S: C2722.1 C2732.1 R8308.2 T8309.1 U2400.AF2 U2400.AG1 U2400.AM15 U2400.AP12
+V1P2S_EDP_8622: C7108.1 C7110.1 C7112.1 C7166.1 L7102.2 U7107.6 U7107.15 U7107.27
+V1P2S_PMIC: C8318.1 R8308.1 U8201.C10
+V1P2SX: C2709.1 C2710.1 C2713.1 C2825.1 R8309.2 T8310.1 U2400.AE1 U2400.AH27 U2400.AK45 U2400.AP16 U2400.BV36 U2400.BW35 U2400.M40 U2400.P44
+V1P2SX_PMIC: C8317.1 R8309.1 U8201.B10
+V1P05S: C2733.1 C2734.1 C2735.1 C2736.1 C2737.1 R8209.1 T8203.1 U2400.A30 U2400.A33 U2400.A35 U2400.AC37 U2400.AD36 U2400.AK39 U2400.B36 U2400.BW39 U2400.W39
+V1P05S_FB: JP8202.2 U8201.P8
+V1P05S_LX: L8212.2 U8201.P10
+V1P05S_PMIC: C8237.1 C8273.1 JP8202.1 L8212.1 R8209.2
+V1P8_EC: C3008.1 C3009.1 C3010.1 C3011.1 L3003.2 R3001.1 R3036.2 R3037.2 R3078.2 R3079.2 R8128.2 R8131.1 T8105.1 U3001.30 U3001.51 U3001.54 U3001.55
+V1P8A: C3318.1 C5414.1 C8316.1 C8336.1 Q2644.5 Q2650.2 Q2650.5 Q8303.2 R0508.1 R0509.1 R0510.1 R2630.1 R2635.2 R2636.2 R2640.1 R2645.1 R2649.1 R2659.2 R2676.1 R2677.2 R2688.1 R2692.1 R2720.2 R3343.1 R3344.1 R3352.1 R3803.1 R5204.2 R5427.1 R8213.2 R8317.1 R8431.1 R8435.1 R8448.1 R8826.2 T8206.1 U3304.1 U8201.B8 U8201.G1
+V1P8A_FB: JP8204.1 U8201.C9
+V1P8A_G3: C2747.1 C2748.1 R2720.1 T2706.1 U2400.AD15 U2400.G1 U2400.P21 U2400.P23 U2400.P27
+V1P8A_LX: L8214.1 U8201.A8
+V1P8A_PMIC: C8248.1 C8249.1 C8250.1 JP8204.2 L8214.2 R8213.1
+V1P8S: C7331.1 C7353.1 C7354.1 C7355.1 C7388.1 C7391.1 CON2002.3 Q0902.1 Q0903.1 Q2025.1 Q2655.1 Q2660.2 Q2660.5 Q3101.2 Q5401.2 R0700.1 R0703.1 R0908.1 R0909.1 R0912.1 R1009.2 R1038.1 R1048.2 R1901.1 R2096.1 R2515.1 R2521.1 R2522.1 R2650.2 R2651.2 R2667.2 R2668.2 R2721.2 R3101.2 R3810.1 R5860.1 R7158.1 R7185.1 R7373.1 R7374.1 R8306.2 R8528.1 R8529.1 R8531.1 T8308.1 U7320.A1 U7321.C1 U7322.A1 U7322.B2
+V1P8S_AUD_AVDD: R1009.1 R1046.1 R1047.1
+V1P8S_AUD_D: C1021.2 C1022.1 R1015.1 R1026.2 R1027.2 R1038.2 R1124.2 R1126.2 R1127.2 U1001.43
+V1P8S_AUD_PVDD: C1027.2 C1028.1 R1048.1 U1001.23
+V1P8S_EDP: Q7198.2 Q7198.5 Q7199.2 Q7199.5 R7127.1 R7132.2 R7158.2 R7166.1 R7186.1 R7189.1
+V1P8S_EMMC: C1902.1 C1903.1 C1912.1 C1913.1 C1914.1 R1901.2 T1904.1 U1915.AA3 U1915.AA5 U1915.K6 U1915.W4 U1915.Y4
+V1P8S_PMIC: C8315.1 R8306.1 U8201.B9
+V1P8S_S4: C2706.1 C2707.1 R2721.1 U2400.BF36 U2400.BV22 U2400.BV32 U2400.BW21 U2400.BW33 U2400.P42
+V1P8S_SENSOR: C5810.1 C5812.1 C5820.1 R5824.1 R5842.1 R5860.2 R5866.2 R5867.2 U5801.8 U5801.13 U5804.C1
+V1P8SX: R2121.1 R2134.1 R8307.2 T8307.1
+V1P8SX_2M: C2102.1 C2127.1 CON2101.4 R2102.1 R2121.2 R2179.2
+V1P8SX_PMIC: C8314.1 R8307.1 U8201.B7
+V1P8U: R1625.1 R8318.2
+V1P8U_EN#: Q8303.1 R8317.2 U8201.D10
+V1P8U_LPDDR3: C1618.1 C1619.1 C1705.1 C1707.1 R1625.2 U1601.A15 U1601.A16 U1601.B2 U1601.R1 U1601.T1 U1601.T16 U1701.A15 U1701.A16 U1701.B2 U1701.R1 U1701.T1 U1701.T16
+V1P8U_PMIC: C8335.1 JP8305.1 Q8303.3 R8318.1
+V1P8U_SENSE: JP8305.2 U8201.C8
+V2P85S: C8402.1 R1902.1 R8212.2 T8204.1 U8201.F13
+V2P85S_EMMC: C1900.1 C1904.1 C1905.1 C1915.1 C1916.1 R1902.2 T1905.1 U1915.M6 U1915.N5 U1915.T10 U1915.U9
+V2P85S_FB: JP8203.2 U8201.E13
+V2P85S_LX0: L8213.2 U8201.E14
+V2P85S_LX1: L8213.1 U8201.D14
+V2P85S_PMIC: C8241.1 C8242.1 C8244.1 C8245.1 JP8203.1 R8212.1 U8201.C15
+V2P85SX: R2123.1 R8401.2 T8415.1
+V2P85SX_2M: C2104.1 C2128.1 CON2101.2 R2123.2 R2132.2
+V2P85SX_CCD: C2125.1 R2129.1 R2132.1 U2101.5
+V2P85SX_PMIC: C8401.1 R8401.1 U8201.F14
+V3P3_EC: C3004.1 C3005.1 C3006.1 L3001.1 Q3007.1 R2031.2 R2099.2 R3002.1 R3015.2 R3042.2 R3045.2 R3060.2 R3061.2 R3062.2 R3066.2 R3070.2 R3077.2 R3081.2 R3082.2 R3083.2 R3084.2 R5826.2 R8122.2 R8124.2 R8811.2 T8104.1 U3001.6 U3001.16 U3001.38
+V3P3A: C2124.1 C3801.1 C5407.1 C8306.1 C8406.1 C8407.1 C8411.1 CON3800.50 Q8402.2 Q8405.2 R0511.1 R0512.1 R0513.1 R0514.1 R0515.1 R2015.1 R2030.2 R2683.2 R2702.1 R2722.2 R5424.1 R5825.2 R7004.1 R8310.1 R8405.1 R8437.1 R8835.1 T8312.1 T8314.1 U2101.1 U8201.C5 U8201.G3
+V3P3A_FB: JP8302.1 U8201.F12
+V3P3A_G3: C2724.1 R2722.1 U2400.M20
+V3P3A_LX0: L8301.1 U8201.J14 U8201.J15
+V3P3A_LX1: L8301.2 U8201.G15 U8201.H14
+V3P3A_PMIC: C8320.1 C8321.1 C8322.1 C8323.1 C8324.1 C8325.1 C8326.1 C8367.1 JP8302.2 R8310.2 U8201.F15 U8201.G14
+V3P3S: C0710.1 C2301.2 C3101.1 C7010.1 C7011.1 C7120.2 C7330.1 C7350.1 C7351.1 C7352.1 C7389.1 C7390.1 J3101.32 J3101.34 L7350.1 Q0703.2 Q7001.2 R0753.1 R0755.1 R1017.1 R2016.1 R2723.1 R5101.1 R5110.2 R5861.1 R7103.1 R7122.1 R7143.1 R7183.1 R7194.1 R7370.1 R7371.1 R8404.2 T8419.1 U2301.5 U7141.5 U7320.A2 U7321.B2 U7322.A2
+V3P3S_AUD: C1025.1 C1026.1 C1052.1 R1017.2 U1001.3
+V3P3S_EDP: C7126.1 Q7111.3 R7160.1 R7161.1
+V3P3S_EN#: Q8402.1 R8405.2 U8201.H12
+V3P3S_S4: C2763.1 R2723.2 U2400.BV18 U2400.BW17
+V3P3S_SD: C0706.1 C0707.1 C0708.1 C0713.1 C0787.1 CON0700.4 Q0703.3 R0753.2
+V3P3S_SENSE: JP8402.2 U8201.G13
+V3P3S_SENSOR: C5813.1 C5819.1 C5841.1 R5822.1 R5831.1 R5861.2 U5803.6 U5804.A1
+V3P3S_USBSW: C5101.1 R5101.2 R5105.2 R5106.2 R5107.2 U5101.10
+V3P3S_VIB: CON2002.16 R7005.1
+V3P3SX: L7306.1 R2724.1 R8430.2 T8417.1
+V3P3SX_G3: C2758.1 R2724.2 U2400.J1 U2400.K2
+V3P3U_EN#: T8425.1 U8201.F11
+V5P0S: C8291.1 L7305.1 Q8202.3 R1037.1 R7359.1 R8227.2 T8205.1
+V5P0S_AUD: C1029.1 C1030.1 R1037.2 U1001.2 U1001.46
+V5P0S_EN#: C8290.1 Q8202.1 Q8203.6 R8250.2
+V5P0S_FB: JP8206.1 U8201.M12
+V5P0S_LX: D8201.2 L8216.1 U8201.M14 U8201.M15
+V5P0S_O: Q8202.2 R8218.1 R8227.1 R8250.1 R8302.1
+V5P0S_PMIC: C8260.1 C8261.1 C8262.1 C8263.1 C8264.1 C8265.1 JP8206.2 R8218.2 U8201.L14 U8201.L15
+V5P0S_SUS: C5209.1 C5210.1 C5214.1 CON2002.5 JP8102.2 U5203.2 U5203.3
+V5S: C7356.1 C7357.1 C7358.2 L7304.1 R7358.2 U7311.1
+VBATTBKUP: D2701.1 R2701.1 R2703.1 U8201.E3
+VCC_COMP: C8219.2 U8201.M3
+VCC_GASG: C8916.1 R8944.1 U8901.D1
+VCC_LX0: L8202.2 U8201.L1
+VCC_LX1: L8201.2 U8201.N1
+VCC_LX2: L8203.2 U8201.R3
+VCC_LX3: L8204.2 U8201.R5
+VCC_LX4: L8205.2 U8201.R7
+VDDIO: C7109.2 C7111.1 C7187.1 R7106.2 R7107.1 R7110.1 R7113.1 R7114.1 R7115.1 R7116.1 R7122.2 R7129.2 R7161.2 U7107.32 U7107.42 U7112.8
+VDDIOX: C7106.1 R7103.2 R7160.2 U7107.11 U7107.12
+VDDQ: C8319.1 JP1601.1 R2400.2 R2801.1 R8216.1 U8201.A10 U8201.D11
+VDDQ_FB: JP8205.1 U8201.D12
+VDDQ_LPDDR3: C1601.1 C1602.1 C1603.1 C1604.1 C1605.1 C1606.1 C1607.1 C1608.1 C1609.1 C1709.1 C1710.1 C1711.1 C1712.1 C1713.1 C1714.1 C1715.1 C1716.1 C1717.1 JP1601.2 R1610.2 R1612.1 R1701.1 R1703.2 T1610.1 U1601.A6 U1601.A7 U1601.A9 U1601.A11 U1601.A13 U1601.B9 U1601.B12 U1601.B17 U1601.C3 U1601.C12 U1601.C17 U1601.E1 U1601.E17 U1601.G2 U1601.G12 U1601.G17 U1601.H1 U1601.H16 U1601.K1 U1601.K12 U1601.K17 U1601.L1 U1601.L17 U1601.M2 U1601.M3 U1601.M7 U1601.M10 U1601.M12 U1601.N1 U1601.P17 U1601.R15 U1601.T8 U1601.U2 U1601.U3 U1601.U5 U1601.U7 U1601.U10 U1601.U11 U1601.U14 U1701.A6 U1701.A7 U1701.A9 U1701.A11 U1701.A13 U1701.B9 U1701.B12 U1701.B17 U1701.C3 U1701.C12 U1701.C17 U1701.E1 U1701.E17 U1701.G2 U1701.G12 U1701.G17 U1701.H1 U1701.H16 U1701.K1 U1701.K12 U1701.K17 U1701.L1 U1701.L17 U1701.M2 U1701.M3 U1701.M7 U1701.M10 U1701.M12 U1701.N1 U1701.P17 U1701.R15 U1701.T8 U1701.U2 U1701.U3 U1701.U5 U1701.U7 U1701.U10 U1701.U11 U1701.U14
+VDDQ_LX: L8215.1 U8201.A12 U8201.B12
+VDDQ_PMIC: C8253.1 C8254.1 C8255.1 C8256.1 C8257.1 JP8205.2 L8215.2 R8216.2
+VDDQ_SOC: C2816.1 C2817.1 C2818.1 C2819.1 C2820.1 C2821.1 C2822.1 C2823.1 C2824.1 R2801.2 U2400.AA59 U2400.AC45 U2400.AC59 U2400.AE59 U2400.AR59 U2400.AU59 U2400.AW59 U2400.BA45 U2400.BA59 U2400.BG59 U2400.BJ59 U2400.BL59 U2400.BN59 U2400.G59 U2400.J59 U2400.L59 U2400.N59 U2400.W59
+VDDQ_VTT: JP1602.1 R8301.1 T8305.1
+VDDQ_VTT_FB: JP8301.2 U8201.C14
+VDDQ_VTT_MEM: C1622.1 C1623.1 C1624.1 C1625.1 C1722.1 C1723.1 C1724.1 C1725.1 JP1602.2 R1615.2 R1616.2 R1617.2 R1618.2 R1619.2 R1620.2 R1621.2 R1622.2 R1623.2 R1624.2 R1713.2 R1714.2 R1715.2 R1716.2 R1717.2 R1718.2 R1719.2 R1720.2 R1721.2 R1722.2
+VDDQ_VTT_PMIC: C8302.1 C8303.1 JP8301.1 R8301.2 U8201.C12
AGND_2M: C2104.2 C2128.2 CON2101.1 R2104.2
AGND_AUD: C1001.2 C1002.1 C1005.2 C1006.2 C1007.2 C1008.2 C1025.2 C1026.2 C1027.1 C1028.2 C1040.2 C1052.2 C1053.1 C1102.2 C1106.2 CON2002.14 CON2002.15 R1006.2 R1007.2 R1008.2 R1101.2 T1102.1 U1001.9 U1001.22 U1001.25
AVCC: C3002.1 C3003.1 L3001.2 R3002.2 U3001.45
